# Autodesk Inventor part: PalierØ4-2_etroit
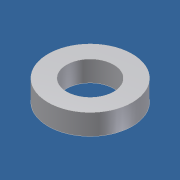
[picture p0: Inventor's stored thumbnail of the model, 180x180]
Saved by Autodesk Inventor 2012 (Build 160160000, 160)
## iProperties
Created: 2011-07
Part Number: PalierØ4-2_etroit
Document SubType Name: Modeling
Designer: domi
Density: 1 g/cm^3
Material: Par défaut
Author: domi
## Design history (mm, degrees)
sketch "Esquisse1"
  geometry: C1 r 2.1 at (0, 0); C2 r 3.75 at (0, 0); 1 further point
  constraints: 2 centre point, 2 coincident
  dimensions: "d0" = 7.5 diameter of C2; "d1" = 4.2 diameter of C1
extrude "Pallier" new body sketch "Esquisse1" distance "d2" = 1.85; taper "d3" = 0 deg
node "Solide1"
node "Corps solides"
node "Corps surfaciques"
